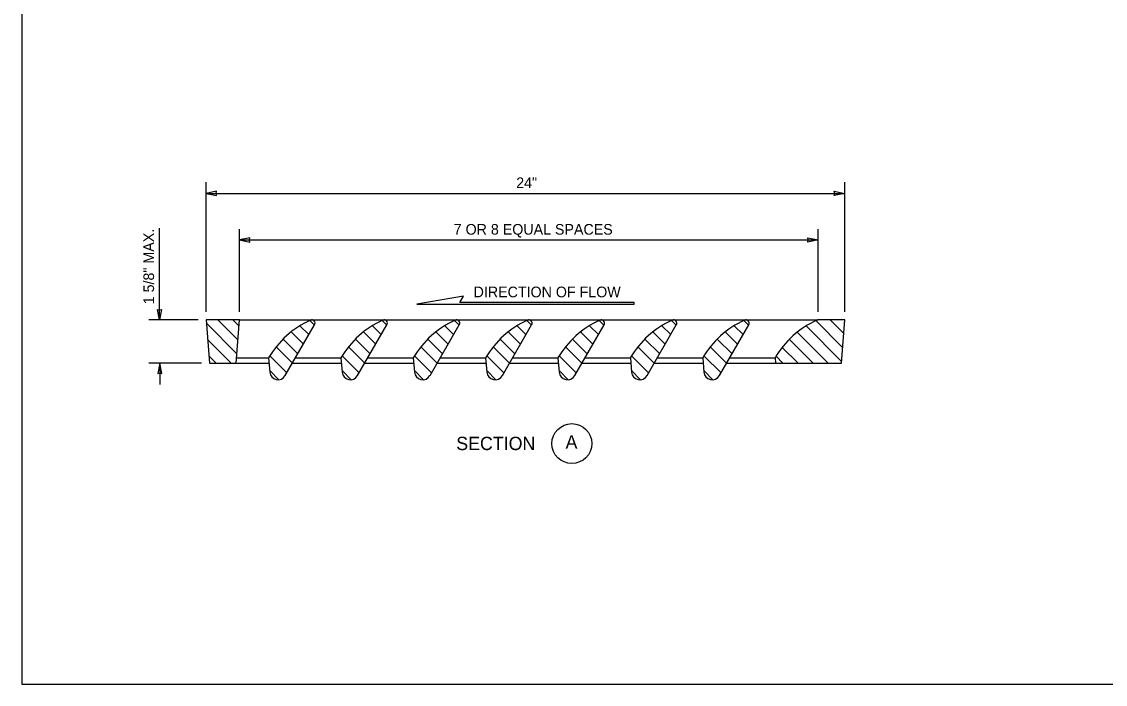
# Model space of a CAD drawing. Extents: x 99862 to 103151, y 100000 to 102076.
# Drawn here: x 99862 to 101491, y 100000 to 100995 of the extents above; entities that cross this region are included whole.
import ezdxf

# ---------------------------------------------------------------- set-up
doc = ezdxf.new("R2010")
doc.units = 0
for name, color, linetype in [('Level 1', 7, 'Continuous'), ('Level 15', 7, 'Continuous'), ('Level 17', 7, 'Continuous'), ('Level 2', 7, 'Continuous'), ('Level 20', 7, 'Continuous'), ('Level 3', 7, 'Continuous'), ('Level 60', 7, 'Continuous'), ('Level 9', 7, 'Continuous')]:
    doc.layers.add(name, color=color, linetype=linetype)

msp = doc.modelspace()

# ---------------------------------------------------------------- linework, layer by layer
at = {"layer": 'Level 1'}
for p, q in [((100189.2, 100547.1), (101059.2, 100547.1)), ((100184.8, 100489.8), (100233.1, 100489.8)), ((100273.5, 100489.8), (100341.9, 100489.8)), ((100382.3, 100489.8), (100450.6, 100489.8)), ((100491, 100489.8), (100559.4, 100489.8)), ((100599.8, 100489.8), (100668.1, 100489.8)), ((100708.5, 100489.8), (100776.9, 100489.8)), ((100817.3, 100489.8), (100885.6, 100489.8)), ((100926, 100489.8), (100994.4, 100489.8)), ((100184.2, 100482.1), (100233.8, 100482.1)), ((100269.1, 100482.1), (100342.5, 100482.1)), ((100377.8, 100482.1), (100451.3, 100482.1)), ((100486.6, 100482.1), (100560, 100482.1)), ((100595.3, 100482.1), (100668.8, 100482.1)), ((100704.1, 100482.1), (100777.5, 100482.1)), ((100812.8, 100482.1), (100886.3, 100482.1)), ((100921.6, 100482.1), (100995, 100482.1))]:
    msp.add_line(p, q, dxfattribs=at)
msp.add_lwpolyline([(99862, 99999.5), (103151, 99999.5), (103151, 102075.5), (99862, 102075.5)], close=True, dxfattribs=at)
at = {"layer": 'Level 15'}
for p, q in [((100139.2, 100559.1), (100139.2, 100753.8)), ((101099.2, 100559.1), (101099.2, 100753.8)), ((100139.2, 100737.1), (101099.2, 100737.1)), ((100069.2, 100547.1), (100069.2, 100684.6)), ((100189.2, 100559.1), (100189.2, 100683.1)), ((101059.2, 100559.1), (101059.2, 100683.1)), ((100189.2, 100667.1), (101059.2, 100667.1)), ((100127.2, 100547.1), (100053, 100547.1)), ((100132.2, 100482.1), (100053.2, 100482.1)), ((100069.8, 100482.1), (100069.8, 100450.1))]:
    msp.add_line(p, q, dxfattribs=at)
for points in [[(100139.2, 100737.1), (100154.9, 100734), (100154.2, 100737.1), (100154.9, 100740.2)], [(101099.2, 100737.1), (101083.5, 100734), (101084.2, 100737.1), (101083.5, 100740.2)], [(100189.2, 100667.1), (100204.9, 100664), (100204.2, 100667.1), (100204.9, 100670.2)], [(101059.2, 100667.1), (101043.5, 100664), (101044.2, 100667.1), (101043.5, 100670.2)], [(100069.2, 100547.1), (100066.1, 100562.8), (100069.2, 100562.1), (100072.3, 100562.8)], [(100069.8, 100482.1), (100066.7, 100466.4), (100069.8, 100467.1), (100072.9, 100466.4)]]:
    msp.add_lwpolyline(points, close=True, dxfattribs=at)
at = {"layer": 'Level 17'}
for p, q in [((100185.3, 100496.2), (100139.6, 100541.9)), ((100186.9, 100517.2), (100157, 100547.1)), ((100188.5, 100538.2), (100179.6, 100547.1)), ((100293.8, 100524.9), (100280.3, 100538.3)), ((100302.1, 100539.2), (100295, 100546.3)), ((100402.5, 100524.9), (100389.1, 100538.3)), ((100410.8, 100539.2), (100403.8, 100546.3)), ((100511.3, 100524.9), (100497.8, 100538.3)), ((100519.6, 100539.2), (100512.5, 100546.3)), ((100620, 100524.9), (100606.6, 100538.3)), ((100628.3, 100539.2), (100621.3, 100546.3)), ((100728.8, 100524.9), (100715.3, 100538.3)), ((100737.1, 100539.2), (100730, 100546.3)), ((100837.5, 100524.9), (100824.1, 100538.3)), ((100845.8, 100539.2), (100838.8, 100546.3)), ((100946.3, 100524.9), (100932.8, 100538.3)), ((100954.6, 100539.2), (100947.5, 100546.3)), ((101094.4, 100484.6), (101041, 100538)), ((101096, 100505.6), (101055.6, 100546)), ((101097.6, 100526.6), (101077.1, 100547.1)), ((100176.8, 100482.1), (100141.5, 100517.4)), ((100277.2, 100496.2), (100255.1, 100518.3)), ((100285.5, 100510.6), (100267.1, 100529)), ((100386, 100496.2), (100363.8, 100518.3)), ((100394.3, 100510.6), (100375.8, 100529)), ((100494.7, 100496.2), (100472.6, 100518.3)), ((100503, 100510.6), (100484.6, 100529)), ((100603.5, 100496.2), (100581.3, 100518.3)), ((100611.8, 100510.6), (100593.3, 100529)), ((100712.2, 100496.2), (100690.1, 100518.3)), ((100720.5, 100510.6), (100702.1, 100529)), ((100821, 100496.2), (100798.8, 100518.3)), ((100829.3, 100510.6), (100810.8, 100529)), ((100929.7, 100496.2), (100907.6, 100518.3)), ((100938, 100510.6), (100919.6, 100529)), ((101051.6, 100482.1), (101015.9, 100517.8)), ((101074.2, 100482.1), (101027.8, 100528.6)), ((100268.9, 100481.9), (100244.4, 100506.4)), ((100377.7, 100481.9), (100353.2, 100506.4)), ((100486.4, 100481.9), (100461.9, 100506.4)), ((100595.2, 100481.9), (100570.7, 100506.4)), ((100703.9, 100481.9), (100679.4, 100506.4)), ((100812.7, 100481.9), (100788.2, 100506.4)), ((100921.4, 100481.9), (100896.9, 100506.4)), ((101029, 100482.1), (101005.2, 100505.8)), ((100154.1, 100482.1), (100143.4, 100492.9)), ((100260.7, 100467.5), (100235.1, 100493.1)), ((100369.4, 100467.5), (100343.8, 100493.1)), ((100478.2, 100467.5), (100452.6, 100493.1)), ((100586.9, 100467.5), (100561.3, 100493.1)), ((100695.7, 100467.5), (100670.1, 100493.1)), ((100804.4, 100467.5), (100778.8, 100493.1)), ((100913.2, 100467.5), (100887.6, 100493.1)), ((101006.3, 100482.1), (100996, 100492.5)), ((100248.4, 100457.1), (100234.8, 100470.8)), ((100357.2, 100457.1), (100343.5, 100470.8)), ((100465.9, 100457.1), (100452.3, 100470.8)), ((100574.7, 100457.1), (100561, 100470.8)), ((100683.4, 100457.1), (100669.8, 100470.8)), ((100792.2, 100457.1), (100778.5, 100470.8)), ((100900.9, 100457.1), (100887.3, 100470.8))]:
    msp.add_line(p, q, dxfattribs=at)
at = {"layer": 'Level 2'}
for points in [[(100184.2, 100482.1), (100189.2, 100547.1), (100139.2, 100547.1), (100144.2, 100482.1), (100184.2, 100482.1)], [(100258.3, 100463.4), (100302.3, 100539.6)], [(100367, 100463.4), (100411, 100539.6)], [(100475.8, 100463.4), (100519.8, 100539.6)], [(100584.5, 100463.4), (100628.5, 100539.6)], [(100693.3, 100463.4), (100737.3, 100539.6)], [(100802, 100463.4), (100846, 100539.6)], [(100910.8, 100463.4), (100954.8, 100539.6)], [(100994.4, 100489.8), (100995, 100482.1), (101094.2, 100482.1), (101099.2, 100547.1), (101059.2, 100547.1)], [(100233.1, 100489.8), (100235, 100468.5)], [(100341.9, 100489.8), (100343.7, 100468.5)], [(100450.6, 100489.8), (100452.5, 100468.5)], [(100559.4, 100489.8), (100561.2, 100468.5)], [(100668.1, 100489.8), (100670, 100468.5)], [(100776.9, 100489.8), (100778.7, 100468.5)], [(100885.6, 100489.8), (100887.5, 100468.5)]]:
    msp.add_lwpolyline(points, dxfattribs=at)
for centre, radius, start, end in [((100354.1, 100419.3), 140, 114.5682, 149.7715), ((100298, 100542.1), 5, 330, 114.5682), ((100462.8, 100419.3), 140, 114.5682, 149.7715), ((100406.7, 100542.1), 5, 330, 114.5682), ((100571.6, 100419.3), 140, 114.5682, 149.7715), ((100515.5, 100542.1), 5, 330, 114.5682), ((100680.3, 100419.3), 140, 114.5682, 149.7715), ((100624.2, 100542.1), 5, 330, 114.5682), ((100789.1, 100419.3), 140, 114.5682, 149.7715), ((100733, 100542.1), 5, 330, 114.5682), ((100897.8, 100419.3), 140, 114.5682, 149.7715), ((100841.7, 100542.1), 5, 330, 114.5682), ((101006.6, 100419.3), 140, 114.5682, 149.7715), ((100950.5, 100542.1), 5, 330, 114.5682), ((101115.3, 100419.3), 140, 114.5682, 149.7715), ((101059.2, 100542.1), 5, 90, 114.5682), ((100247.4, 100469.6), 12.5, 185, 330), ((100356.2, 100469.6), 12.5, 185, 330), ((100464.9, 100469.6), 12.5, 185, 330), ((100573.7, 100469.6), 12.5, 185, 330), ((100682.4, 100469.6), 12.5, 185, 330), ((100791.2, 100469.6), 12.5, 185, 330), ((100899.9, 100469.6), 12.5, 185, 330)]:
    msp.add_arc(centre, radius, start, end, dxfattribs=at)
at = {"layer": 'Level 3'}
msp.add_lwpolyline([(100782.7, 100573), (100520.4, 100573), (100526.1, 100582.9), (100456.1, 100570.5), (100782.7, 100570.5)], close=True, dxfattribs=at)
at = {"layer": 'Level 60'}
msp.add_line((99862, 99999.5), (99862, 99999.5), dxfattribs=at)
at = {"layer": 'Level 9'}
msp.add_circle((100689, 100361.2), 30, dxfattribs=at)

# ---------------------------------------------------------------- texts
at = {"layer": 'Level 20'}
for s, height, p in [('24"', 16, (100605.3, 100745.1)), ('7 OR 8 EQUAL SPACES', 16, (100511.4, 100675.1)), ('DIRECTION OF FLOW', 16, (100541.3, 100581)), ('SECTION', 20, (100515.2, 100351.4)), ('A', 20, (100679.5, 100353.6))]:
    msp.add_text(s, height=height, dxfattribs=at).set_placement(p)
msp.add_text('1 5/8" MAX.', height=16, rotation=90, dxfattribs=at).set_placement((100061, 100570.5))

doc.saveas('drawing.dxf')
